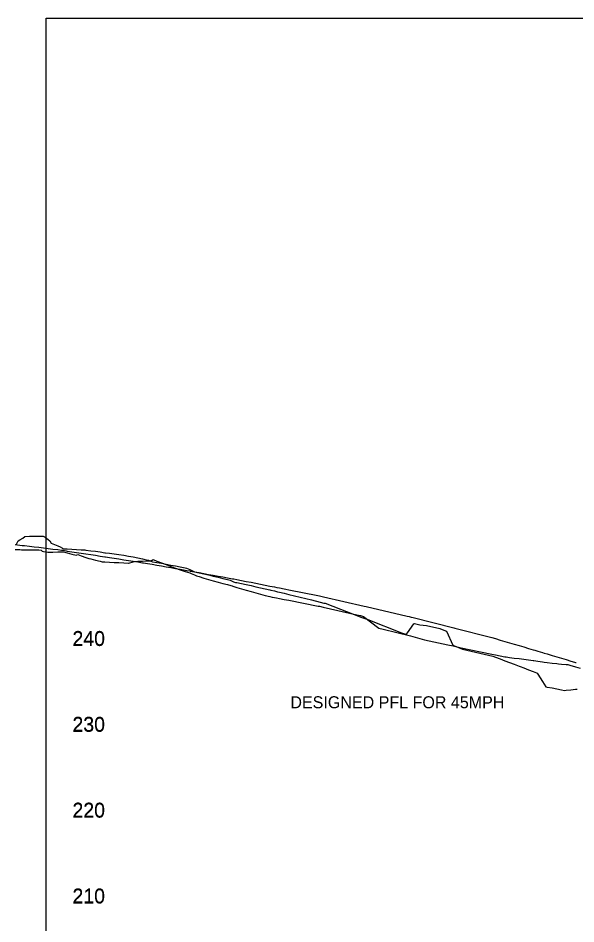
# Model space of a CAD drawing. Extents: x 2224795 to 2228395, y 930927 to 933127.
# Drawn here: x 2225458 to 2225784, y 932027 to 932554 of the extents above; entities that cross this region are included whole.
import ezdxf

# ---------------------------------------------------------------- set-up
doc = ezdxf.new("R2010")
doc.units = 0
for name, color, linetype in [('BR_EXIST_GROUND_LT', 7, 'Continuous'), ('BR_EXIST_GROUND_RT', 7, 'Continuous'), ('BR_USER NOTES', 7, 'Continuous'), ('RD_DDB_ElevTX', 7, 'Continuous'), ('RD_DDB_Profile_EX', 7, 'Continuous'), ('RD_SHT_ShtClip', 7, 'Continuous')]:
    doc.layers.add(name, color=color, linetype=linetype)

msp = doc.modelspace()

# ---------------------------------------------------------------- linework, layer by layer
at = {"layer": 'BR_EXIST_GROUND_LT'}
msp.add_lwpolyline([(2225457.21, 932247.43), (2225458.37, 932249.73), (2225459.34, 932250.35), (2225460.94, 932251.38), (2225462.13, 932252.39), (2225464.84, 932252.41), (2225467.59, 932252.43), (2225470.34, 932252.45), (2225472.91, 932252.46), (2225474.08, 932251.92), (2225475.84, 932250.52), (2225476.85, 932249.72), (2225477.55, 932248.44), (2225478.59, 932247.99), (2225481.34, 932246.82), (2225482.71, 932246.22), (2225484.09, 932245.53), (2225484.78, 932245.19), (2225486.84, 932245.1), (2225489.59, 932244.96), (2225492.34, 932244.8), (2225495.09, 932244.63), (2225497.19, 932244.48), (2225497.84, 932244.4), (2225500.59, 932244.05), (2225503.34, 932243.69), (2225506.09, 932243.3), (2225508.84, 932242.89), (2225509.26, 932242.82), (2225511.6, 932242.55), (2225514.35, 932242.21), (2225517.1, 932241.85), (2225519.85, 932241.46), (2225522.6, 932240.94), (2225525.35, 932240.39), (2225528.1, 932239.81), (2225530.85, 932239.22), (2225533.77, 932238.56), (2225534.22, 932238.46), (2225534.63, 932238.37), (2225536.61, 932237.63), (2225539.1, 932237.21), (2225541.85, 932236.73), (2225544.6, 932236.22), (2225547.35, 932235.7), (2225550.1, 932235.15), (2225552.85, 932234.59), (2225555.6, 932234), (2225556.39, 932233.82), (2225558.35, 932232.99), (2225561.1, 932231.82), (2225563.85, 932231.21), (2225566.6, 932230.59), (2225569.35, 932229.95), (2225572.1, 932229.29), (2225574.85, 932228.62), (2225577.6, 932227.93), (2225580.35, 932227.22), (2225581.95, 932226.81), (2225583.1, 932226.24), (2225583.81, 932225.88), (2225585.09, 932225.58), (2225585.85, 932225.42), (2225588.6, 932224.86), (2225591.35, 932224.28), (2225594.1, 932223.68), (2225596.85, 932223.08), (2225599.6, 932222.47), (2225602.35, 932221.84), (2225605.1, 932221.2), (2225605.58, 932221.09), (2225607.85, 932220.57), (2225609.59, 932220.16), (2225610.6, 932219.92), (2225613.35, 932219.24), (2225616.1, 932218.56), (2225629.28, 932215.32), (2225634.43, 932214.09), (2225636.56, 932213.57), (2225637.29, 932213.4), (2225658.62, 932205.18), (2225662.21, 932203.92), (2225681.89, 932196.21), (2225684.27, 932195.49), (2225684.71, 932195.4), (2225685.32, 932196.19), (2225689.01, 932201.51), (2225689.39, 932201.61), (2225692.59, 932200.84), (2225696.37, 932200.44), (2225704.26, 932198.65), (2225707.52, 932197.39), (2225708.05, 932197.08), (2225711.85, 932188.92), (2225717.46, 932186.74), (2225735.02, 932182.64), (2225736.64, 932182.02), (2225739.39, 932181), (2225742.14, 932179.96), (2225744.88, 932178.91), (2225747.63, 932177.85), (2225750.38, 932176.79), (2225751, 932176.55), (2225753.13, 932175.73), (2225755.88, 932174.67), (2225758.63, 932173.6), (2225760.51, 932172.86), (2225761.02, 932172.66), (2225761.37, 932172.11), (2225764.12, 932167.77), (2225766.05, 932164.72), (2225766.87, 932164.58), (2225769.62, 932164.08), (2225772.37, 932163.56), (2225775.11, 932163.01), (2225776.86, 932162.65), (2225777.86, 932162.76), (2225780.61, 932163.07), (2225783.36, 932163.35), (2225784.22, 932163.44)], dxfattribs=at)
at = {"layer": 'BR_EXIST_GROUND_RT'}
msp.add_lwpolyline([(2225456.59, 932244.66), (2225458.71, 932244.7), (2225459.34, 932244.65), (2225460.22, 932244.57), (2225462.09, 932244.58), (2225464.84, 932244.58), (2225467.59, 932244.6), (2225469.78, 932244.61), (2225470.34, 932244.54), (2225471.71, 932244.36), (2225472.25, 932243.8), (2225473.09, 932243.63), (2225474.33, 932243.38), (2225475.51, 932243.17), (2225475.84, 932243.17), (2225478.59, 932243.23), (2225481.34, 932243.3), (2225484.09, 932243.36), (2225484.67, 932243.32), (2225486.84, 932242.73), (2225489.59, 932242), (2225492.05, 932241.35), (2225493.16, 932241.81), (2225495.09, 932241.09), (2225497.84, 932240.07), (2225499.5, 932239.46), (2225500.59, 932239.31), (2225503.34, 932238.61), (2225506.09, 932237.92), (2225507.28, 932237.63), (2225508.84, 932237.52), (2225511.6, 932237.36), (2225514.35, 932237.21), (2225517.1, 932237.07), (2225519.85, 932236.96), (2225522.6, 932236.86), (2225522.9, 932236.85), (2225525.35, 932237.55), (2225526.14, 932237.79), (2225528.1, 932237.86), (2225530.85, 932237.98), (2225533.6, 932238.12), (2225535.35, 932238.23), (2225536.35, 932238.56), (2225537.09, 932238.82), (2225539.1, 932238.02), (2225541.85, 932236.96), (2225544.6, 932235.92), (2225547.35, 932234.9), (2225550.1, 932233.9), (2225552.85, 932232.93), (2225555.6, 932231.98), (2225558.35, 932231.05), (2225559.22, 932230.76), (2225561.1, 932229.94), (2225562.39, 932229.38), (2225563.85, 932228.93), (2225566.6, 932228.1), (2225569.35, 932227.29), (2225572.1, 932226.5), (2225574.85, 932225.73), (2225577.6, 932224.99), (2225580.35, 932224.27), (2225582.36, 932223.75), (2225583.1, 932223.48), (2225583.44, 932223.36), (2225585.85, 932222.63), (2225588.6, 932221.81), (2225591.35, 932221.01), (2225594.1, 932220.23), (2225596.85, 932219.47), (2225599.6, 932218.73), (2225602.35, 932218.02), (2225605.1, 932217.32), (2225606.46, 932216.98), (2225607.85, 932216.72), (2225608.9, 932216.52), (2225610.6, 932216.2), (2225613.35, 932215.68), (2225616.1, 932215.15), (2225633.2, 932211.8), (2225634.05, 932211.64), (2225636.18, 932211.22), (2225655.76, 932206.75), (2225657.99, 932206.26), (2225659.62, 932205.76), (2225668.71, 932198.99), (2225671.1, 932198.31), (2225687, 932194.4), (2225688.44, 932194.05), (2225695.28, 932192.08), (2225708.86, 932189.24), (2225711.99, 932188.54), (2225715.74, 932187.7), (2225734.46, 932183.69), (2225736.64, 932183.29), (2225739.39, 932182.79), (2225742.14, 932182.3), (2225742.8, 932182.18), (2225744.88, 932181.89), (2225747.63, 932181.52), (2225750.38, 932181.15), (2225753.13, 932180.8), (2225755.88, 932180.45), (2225758.63, 932180.11), (2225758.98, 932180.07), (2225761.37, 932179.69), (2225764.12, 932179.26), (2225765.07, 932179.11), (2225766.87, 932178.9), (2225769.62, 932178.59), (2225772.37, 932178.28), (2225773.42, 932178.16), (2225775.11, 932178), (2225777.86, 932177.75), (2225778.77, 932177.67), (2225780.61, 932177.17), (2225782.71, 932176.59), (2225783.36, 932176.39), (2225786.11, 932175.53)], dxfattribs=at)
at = {"layer": 'RD_DDB_Profile_EX'}
msp.add_lwpolyline([(2225456.59, 932247.59), (2225459.34, 932247.27), (2225460.62, 932247.12), (2225462.09, 932246.99), (2225464.84, 932246.67), (2225467.59, 932246.34), (2225470.34, 932246.01), (2225473.09, 932245.68), (2225475.84, 932245.35), (2225478.59, 932245.01), (2225481.34, 932244.67), (2225483.55, 932244.39), (2225484.29, 932244.27), (2225486.37, 932243.93), (2225486.84, 932243.86), (2225489.59, 932243.45), (2225492.34, 932243.04), (2225495.09, 932242.63), (2225497.84, 932242.21), (2225500.59, 932241.79), (2225503.34, 932241.37), (2225506.09, 932240.95), (2225508.84, 932240.53), (2225509.28, 932240.46), (2225511.6, 932240.1), (2225514.35, 932239.67), (2225517.1, 932239.24), (2225519.85, 932238.81), (2225522.6, 932238.37), (2225525.35, 932237.94), (2225528.1, 932237.5), (2225530.85, 932237.06), (2225531.46, 932236.96), (2225533.71, 932236.56), (2225536.35, 932236.1), (2225539.1, 932235.63), (2225541.85, 932235.15), (2225544.6, 932234.67), (2225547.35, 932234.19), (2225550.1, 932233.7), (2225552.85, 932233.22), (2225555.6, 932232.73), (2225556.59, 932232.55), (2225558.35, 932232.24), (2225558.7, 932232.18), (2225561.1, 932231.75), (2225563.85, 932231.25), (2225566.6, 932230.76), (2225569.35, 932230.26), (2225572.1, 932229.77), (2225574.85, 932229.27), (2225577.6, 932228.76), (2225580.35, 932228.26), (2225583.26, 932227.73), (2225583.68, 932227.65), (2225584.07, 932227.57), (2225585.85, 932227.23), (2225588.6, 932226.7), (2225591.35, 932226.16), (2225594.1, 932225.62), (2225596.85, 932225.09), (2225599.6, 932224.55), (2225602.35, 932224), (2225605.1, 932223.46), (2225607.85, 932222.91), (2225609.05, 932222.67), (2225610.6, 932222.36), (2225613.35, 932221.82), (2225614.48, 932221.59), (2225616.1, 932221.27), (2225633.1, 932217.85), (2225634.05, 932217.67), (2225636.32, 932217.22), (2225660.15, 932211.69), (2225661.3, 932211.44), (2225685.08, 932205.92), (2225686.31, 932205.65), (2225687.46, 932205.38), (2225688.66, 932205.1), (2225712.44, 932199.05), (2225712.95, 932198.93), (2225734.61, 932193.41), (2225736.64, 932192.81), (2225739.39, 932192), (2225742.14, 932191.19), (2225744.88, 932190.38), (2225747.63, 932189.57), (2225750.38, 932188.76), (2225753.13, 932187.95), (2225755.88, 932187.14), (2225758.63, 932186.33), (2225759.62, 932186.03), (2225761.37, 932185.52), (2225764.12, 932184.7), (2225765.11, 932184.41), (2225766.87, 932183.89), (2225769.62, 932183.07), (2225772.37, 932182.25), (2225775.11, 932181.43), (2225777.86, 932180.6), (2225780.61, 932179.78), (2225782.65, 932179.17), (2225783.36, 932178.93), (2225783.67, 932178.83)], dxfattribs=at)
at = {"layer": 'RD_SHT_ShtClip'}
msp.add_lwpolyline([(2225474.62, 932554.3), (2227274.62, 932554.3), (2227274.62, 931454.3), (2225474.62, 931454.3)], close=True, dxfattribs=at)

# ---------------------------------------------------------------- texts
at = {"layer": 'BR_USER NOTES'}
msp.add_text('DESIGNED PFL FOR 45MPH', height=7, dxfattribs=at).set_placement((2225617.03, 932152.24))
at = {"layer": 'RD_DDB_ElevTX'}
for s, p in [('240', (2225489.98, 932188.76)), ('240', (2225489.98, 932188.51)), ('230', (2225489.98, 932138.76)), ('230', (2225489.98, 932138.51)), ('220', (2225489.98, 932088.76)), ('220', (2225489.98, 932088.51)), ('210', (2225489.98, 932038.76)), ('210', (2225489.98, 932038.51))]:
    msp.add_text(s, height=8.5, dxfattribs=at).set_placement(p)

doc.saveas('drawing.dxf')
